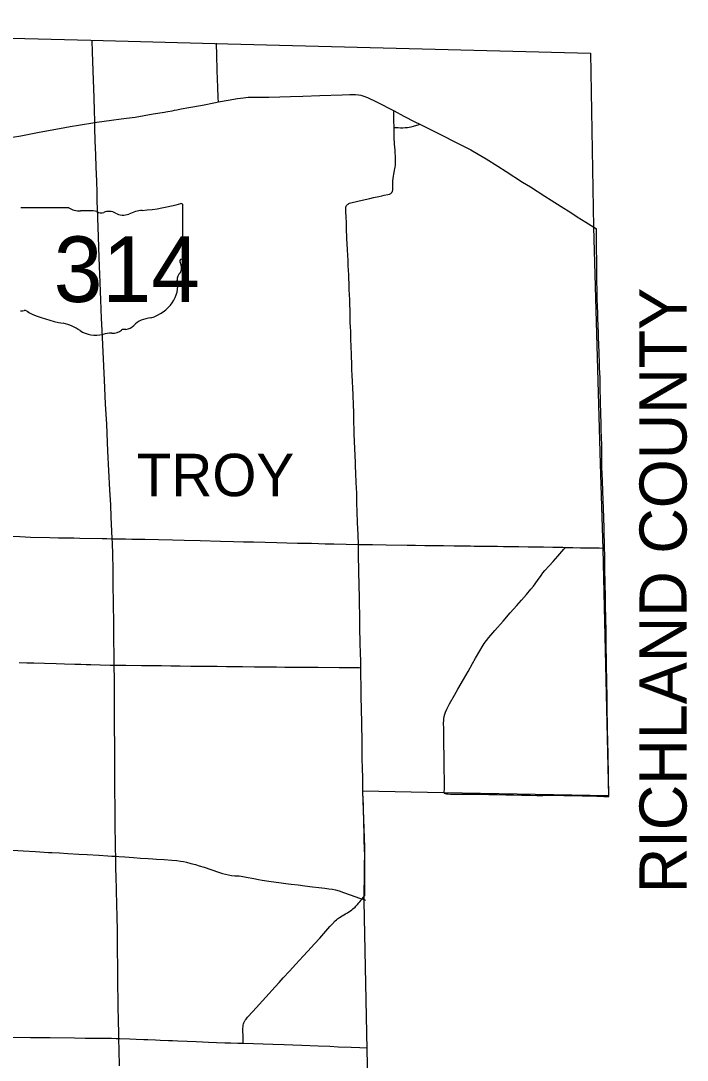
# Model space of a CAD drawing. Extents: x 1815539 to 1947826, y 273303 to 993194.
# Drawn here: x 1921002 to 1935160, y 965571 to 987636 of the extents above; entities that cross this region are included whole.
import ezdxf

# ---------------------------------------------------------------- set-up
doc = ezdxf.new("R2010")
doc.units = 0
for name, color, linetype in [('GM_X_Adjacent_County_Text', 7, 'Continuous'), ('GM_X_County', 7, 'Continuous'), ('GM_X_County_Road', 7, 'Continuous'), ('GM_X_State_Route', 7, 'Continuous'), ('GM_X_Township_Road', 7, 'Continuous'), ('GM_X_Township_Text', 7, 'Continuous'), ('SC_Shading3', 7, 'Continuous')]:
    doc.layers.add(name, color=color, linetype=linetype)

msp = doc.modelspace()

# ---------------------------------------------------------------- linework, layer by layer
at = {"layer": 'GM_X_County'}
msp.add_lwpolyline([(1905517, 987636), (1906801, 987606), (1908915, 987558), (1916031, 987559), (1916031, 987390), (1922491, 987223), (1925127, 987155), (1933106, 986948), (1933172, 983252), (1933307, 978234), (1933364, 976428), (1933485, 971181), (1929986, 971246), (1928265, 971283), (1928303, 970087), (1928288, 969028), (1928289, 968947), (1928357, 965797), (1928425, 962614)], dxfattribs=at)
at = {"layer": 'GM_X_County_Road'}
for points in [[(1919598, 976728), (1919624, 976728), (1919785, 976722), (1919899, 976717), (1920096, 976710), (1920424, 976701), (1920686, 976694), (1920981, 976685), (1921211, 976677), (1921621, 976666), (1921801, 976663), (1922129, 976658), (1922259, 976656), (1922734, 976645), (1922831, 976643), (1922947, 976639)], [(1922947, 976639), (1923098, 976636), (1923226, 976635), (1923364, 976634), (1923635, 976629), (1923930, 976624), (1924228, 976619), (1924471, 976611), (1924816, 976602), (1925242, 976589), (1925521, 976583), (1925734, 976577), (1925865, 976575), (1925947, 976573), (1926193, 976566), (1926439, 976561), (1926652, 976554), (1926881, 976549), (1927029, 976546), (1927176, 976543), (1927324, 976540), (1927471, 976535), (1927652, 976531), (1927914, 976526), (1928160, 976521), (1928175, 976521)], [(1928175, 976521), (1928291, 976518), (1928471, 976515), (1928766, 976511), (1929209, 976506), (1929390, 976503), (1929586, 976500), (1929734, 976498), (1929979, 976494), (1930209, 976490), (1930356, 976489), (1930553, 976487), (1930635, 976486), (1930717, 976486), (1930880, 976484), (1930995, 976482), (1931126, 976481), (1931257, 976479), (1931388, 976477), (1931585, 976474), (1931781, 976470), (1931896, 976468), (1932109, 976467), (1932306, 976465), (1932519, 976459), (1932572, 976457)], [(1932572, 976457), (1932733, 976453), (1932896, 976449), (1933044, 976447), (1933175, 976446), (1933290, 976445), (1933388, 976443), (1933406, 976443)], [(1920968, 974014), (1921132, 974008), (1921213, 974006), (1921279, 974005), (1921508, 973997), (1921753, 973990), (1921934, 973985), (1922147, 973979), (1922278, 973976), (1922392, 973974), (1922491, 973970), (1922687, 973964), (1922899, 973959), (1922987, 973958)], [(1920708, 966058), (1921206, 966052), (1921628, 966050), (1922140, 966044), (1922370, 966041), (1922567, 966039), (1922731, 966037), (1922928, 966037), (1923026, 966034), (1923085, 966030)], [(1923085, 966030), (1923108, 966029), (1923321, 966023), (1923452, 966017), (1923616, 966011), (1923698, 966009), (1923862, 966002), (1923960, 965996), (1924140, 965990), (1924222, 965987), (1924337, 965982), (1924534, 965974), (1924730, 965966), (1924862, 965961), (1924993, 965956), (1925157, 965950), (1925337, 965942), (1925468, 965938), (1925616, 965933), (1925725, 965931)], [(1925725, 965931), (1925730, 965931), (1925944, 965924), (1926354, 965912), (1926599, 965902), (1926779, 965895), (1926975, 965887), (1927320, 965876), (1927567, 965866), (1927745, 965858), (1928024, 965846), (1928202, 965838), (1928360, 965834)]]:
    msp.add_lwpolyline(points, dxfattribs=at)
at = {"layer": 'GM_X_State_Route'}
for points in [[(1923098, 965449), (1923091, 965777), (1923085, 966030), (1923083, 966089), (1923075, 966466), (1923071, 966663), (1923063, 967352), (1923063, 967549), (1923063, 967630), (1923062, 967663), (1923060, 967795), (1923058, 967926), (1923057, 968090), (1923055, 968320), (1923054, 968402), (1923051, 968533), (1923050, 968648), (1923045, 968845), (1923043, 968927), (1923037, 969123), (1923034, 969238), (1923029, 969418), (1923024, 969681), (1923021, 969829), (1923019, 969899), (1923015, 970042), (1923011, 970239), (1923009, 970468), (1923008, 970583), (1923008, 970714), (1923006, 970829), (1923005, 971059), (1923003, 971174), (1923002, 971239), (1923002, 971305), (1923002, 971452), (1923002, 971534), (1923000, 971649), (1922998, 971780), (1922997, 971928), (1922997, 972026), (1922999, 972223), (1922995, 972666), (1922994, 972814), (1922994, 972978), (1922994, 973125), (1922993, 973257), (1922992, 973388), (1922991, 973519), (1922991, 973634), (1922991, 973732), (1922989, 973864), (1922988, 973946), (1922987, 973958), (1922985, 974110), (1922984, 974274), (1922982, 974389), (1922979, 974651), (1922976, 974881), (1922973, 975226), (1922970, 975373), (1922966, 975570), (1922964, 975734), (1922965, 975882), (1922963, 975997), (1922958, 976309), (1922951, 976555), (1922947, 976639), (1922940, 976801), (1922925, 977096), (1922912, 977357), (1922895, 977677), (1922876, 978087), (1922855, 978496), (1922827, 979070), (1922804, 979496), (1922794, 979677), (1922782, 980004), (1922753, 980611), (1922730, 981070), (1922718, 981316), (1922702, 981709), (1922695, 981889), (1922679, 982266), (1922674, 982414), (1922661, 982824), (1922654, 983053), (1922641, 983447), (1922633, 983658), (1922628, 983793), (1922623, 983988), (1922617, 984231), (1922604, 984530), (1922596, 984790), (1922584, 985086), (1922577, 985361), (1922573, 985475), (1922572, 985511), (1922567, 985725), (1922559, 986003), (1922549, 986381), (1922527, 986971), (1922516, 987224)], [(1920826, 985162), (1921004, 985192), (1921148, 985221), (1921358, 985261), (1921551, 985296), (1921825, 985349), (1922050, 985391), (1922228, 985421), (1922573, 985475), (1922617, 985481), (1922926, 985526), (1923137, 985556), (1923251, 985569), (1923429, 985593), (1923623, 985624), (1923817, 985659), (1924054, 985697), (1924082, 985703), (1924125, 985709), (1924219, 985726), (1924267, 985735), (1924315, 985745), (1924411, 985763), (1924571, 985794), (1924862, 985847), (1925136, 985899), (1925204, 985912), (1925410, 985950), (1925604, 985984), (1925734, 986002), (1925832, 986011), (1925931, 986014), (1926275, 986012), (1926505, 986018), (1926734, 986026), (1926996, 986035), (1927357, 986048), (1927832, 986067), (1927996, 986073), (1928111, 986072), (1928177, 986066), (1928226, 986057), (1928289, 986038), (1928365, 986006), (1928557, 985912), (1928931, 985721), (1929141, 985613), (1929375, 985494), (1929480, 985441), (1929580, 985391), (1929917, 985221), (1930268, 985044), (1930560, 984894), (1930718, 984806), (1930887, 984705), (1931137, 984548), (1931317, 984434), (1931663, 984213), (1931829, 984108), (1932133, 983915), (1932272, 983828), (1932480, 983696), (1932687, 983563), (1932825, 983475), (1933005, 983361), (1933231, 983217)]]:
    msp.add_lwpolyline(points, dxfattribs=at)
at = {"layer": 'GM_X_Township_Road'}
for points in [[(1925204, 985912), (1925197, 985999), (1925185, 986237), (1925182, 986386), (1925176, 986584), (1925167, 986896), (1925160, 987157)], [(1928931, 985368), (1928929, 985524), (1928930, 985702), (1928931, 985721)], [(1928931, 985368), (1929018, 985367), (1929072, 985366), (1929119, 985366), (1929169, 985368), (1929218, 985370), (1929254, 985374), (1929297, 985384), (1929345, 985397), (1929462, 985435), (1929480, 985441)], [(1927924, 983187), (1927923, 983238), (1927922, 983306), (1927919, 983384), (1927916, 983436), (1927913, 983500), (1927909, 983550), (1927907, 983599), (1927908, 983630), (1927908, 983647), (1927909, 983664), (1927911, 983679), (1927915, 983697), (1927923, 983711), (1927932, 983724), (1927944, 983736), (1927957, 983746), (1927971, 983754), (1927986, 983761), (1928017, 983770), (1928161, 983805), (1928257, 983828), (1928417, 983865), (1928497, 983883), (1928609, 983909), (1928673, 983922), (1928721, 983933), (1928801, 983950), (1928833, 983958), (1928848, 983964), (1928863, 983972), (1928876, 983982), (1928887, 983994), (1928896, 984008), (1928902, 984023), (1928905, 984039), (1928907, 984055), (1928907, 984104), (1928906, 984187), (1928907, 984236), (1928911, 984285), (1928917, 984334), (1928925, 984382), (1928932, 984414), (1928944, 984462), (1928952, 984493), (1928958, 984525), (1928963, 984574), (1928964, 984640), (1928963, 984706), (1928953, 984886), (1928944, 985017), (1928936, 985164), (1928935, 985214), (1928931, 985368)], [(1928085, 978965), (1928080, 979106), (1928078, 979196), (1928074, 979344), (1928071, 979459), (1928061, 979704), (1928043, 980114), (1928038, 980229), (1928033, 980409), (1928031, 980457), (1928030, 980505), (1928028, 980538), (1928022, 980735), (1928016, 980866), (1928014, 980932), (1928011, 981030), (1928006, 981145), (1928003, 981227), (1927997, 981424), (1927990, 981686), (1927984, 981850), (1927981, 981899), (1927978, 981981), (1927968, 982243), (1927959, 982439), (1927954, 982538), (1927949, 982668), (1927944, 982766), (1927935, 982912), (1927931, 982994), (1927927, 983074), (1927925, 983174), (1927924, 983187)], [(1933347, 978263), (1933347, 978285), (1933346, 978384), (1933343, 978597), (1933337, 978827), (1933334, 978925), (1933331, 979105), (1933327, 979269), (1933323, 979367), (1933319, 979465), (1933317, 979562), (1933315, 979644), (1933314, 979759), (1933312, 979874), (1933310, 979989), (1933309, 980038), (1933303, 980185), (1933299, 980250), (1933297, 980300), (1933295, 980365), (1933288, 980578), (1933282, 980774), (1933278, 980905), (1933274, 981020), (1933269, 981151), (1933262, 981332), (1933259, 981446), (1933255, 981561), (1933250, 981743), (1933247, 981857), (1933244, 981953), (1933243, 982068), (1933241, 982215), (1933240, 982476), (1933238, 982590), (1933236, 982745), (1933234, 982894), (1933231, 983217)], [(1928175, 976521), (1928167, 976721), (1928157, 976984), (1928149, 977213), (1928144, 977393), (1928138, 977607), (1928130, 977836), (1928123, 978033), (1928116, 978180), (1928113, 978262), (1928107, 978409), (1928095, 978704), (1928088, 978868), (1928085, 978965)], [(1933406, 976443), (1933406, 976483), (1933401, 976614), (1933399, 976680), (1933398, 976745), (1933395, 976860), (1933388, 977089), (1933380, 977285), (1933373, 977465), (1933366, 977646), (1933359, 977875), (1933349, 978154), (1933347, 978263)], [(1928226, 973903), (1928223, 974049), (1928221, 974213), (1928214, 974426), (1928210, 974524), (1928207, 974655), (1928204, 974901), (1928196, 975377), (1928190, 975672), (1928185, 975934), (1928182, 976049), (1928180, 976197), (1928178, 976312), (1928176, 976492), (1928175, 976521)], [(1929994, 971238), (1929996, 971266), (1930001, 971325), (1930003, 971407), (1930002, 971538), (1929998, 971735), (1929996, 971882), (1929993, 972079), (1929992, 972227), (1929989, 972407), (1929988, 972604), (1929985, 972735), (1929986, 972784), (1929989, 972816), (1929998, 972865), (1930010, 972913), (1930025, 972959), (1930050, 973020), (1930072, 973064), (1930109, 973135), (1930215, 973322), (1930289, 973450), (1930404, 973649), (1930503, 973819), (1930599, 973990), (1930663, 974105), (1930753, 974261), (1930804, 974345), (1930849, 974414), (1930897, 974481), (1930948, 974545), (1931074, 974696), (1931247, 974893), (1931400, 975064), (1931541, 975224), (1931639, 975334), (1931747, 975458), (1931840, 975572), (1931891, 975637), (1931979, 975755), (1932056, 975861), (1932095, 975914), (1932137, 975964), (1932224, 976063), (1932311, 976159), (1932411, 976268), (1932497, 976367), (1932539, 976417), (1932572, 976457)], [(1933493, 971169), (1933492, 971204), (1933485, 971576), (1933477, 972069), (1933468, 972594), (1933465, 972758), (1933462, 972939), (1933458, 973217), (1933456, 973349), (1933455, 973529), (1933451, 973726), (1933448, 973841), (1933445, 974087), (1933440, 974317), (1933436, 974662), (1933431, 974973), (1933426, 975203), (1933423, 975334), (1933422, 975482), (1933419, 975613), (1933411, 976073), (1933409, 976303), (1933406, 976434), (1933406, 976443)], [(1922987, 973958), (1923237, 973956), (1923568, 973953), (1923752, 973952), (1923994, 973947), (1924187, 973942), (1924387, 973939), (1924616, 973935), (1924895, 973933), (1925092, 973933), (1925174, 973933), (1925372, 973930), (1925714, 973927), (1925967, 973924), (1926075, 973922), (1926223, 973920), (1926436, 973918), (1926615, 973916), (1926830, 973914), (1927126, 973913), (1927323, 973911), (1927765, 973909), (1928062, 973905), (1928189, 973904), (1928226, 973903)], [(1928272, 971231), (1928267, 971504), (1928267, 971592), (1928263, 971739), (1928261, 971820), (1928258, 971918), (1928256, 972131), (1928254, 972246), (1928251, 972393), (1928247, 972656), (1928244, 972787), (1928240, 972967), (1928239, 973082), (1928236, 973229), (1928232, 973475), (1928228, 973787), (1928226, 973903)], [(1928282, 970925), (1928280, 970985), (1928272, 971231)], [(1929994, 971238), (1930021, 971231), (1930047, 971227), (1930080, 971224), (1930129, 971221), (1930243, 971219), (1930358, 971218), (1930516, 971217), (1930751, 971215), (1930946, 971212), (1931129, 971210), (1931308, 971206), (1931472, 971201), (1931636, 971197), (1931833, 971194), (1931964, 971192), (1932095, 971193), (1932259, 971195), (1932407, 971194), (1932538, 971192), (1932636, 971190), (1932751, 971187), (1932930, 971181), (1932996, 971180), (1933242, 971174), (1933389, 971170), (1933452, 971169), (1933493, 971169)], [(1928295, 970413), (1928292, 970574), (1928289, 970688), (1928284, 970852), (1928282, 970925)], [(1928304, 970054), (1928302, 970100), (1928299, 970198), (1928296, 970312), (1928295, 970413)], [(1920824, 970032), (1921053, 970018), (1921315, 970002), (1921593, 969983), (1921659, 969980), (1921823, 969970), (1922003, 969960), (1922232, 969946), (1922412, 969935), (1922658, 969920), (1922854, 969910), (1922936, 969905), (1923019, 969899)], [(1928312, 969067), (1928311, 969249), (1928310, 969430), (1928311, 969528), (1928312, 969659), (1928311, 969708), (1928311, 969790), (1928309, 969920), (1928304, 970054)], [(1923019, 969899), (1923083, 969894), (1923214, 969886), (1923394, 969873), (1923542, 969862), (1923705, 969851), (1923804, 969844), (1923885, 969839), (1924049, 969829), (1924213, 969817), (1924314, 969809), (1924395, 969799), (1924458, 969788), (1924520, 969774), (1924615, 969749), (1924711, 969723), (1924790, 969700), (1924900, 969666), (1925040, 969619), (1925226, 969555), (1925289, 969536), (1925352, 969519), (1925416, 969505), (1925481, 969494), (1925547, 969488), (1925643, 969482), (1925684, 969480), (1925720, 969473), (1925791, 969458), (1925953, 969426), (1926049, 969408), (1926128, 969394), (1926274, 969371), (1926533, 969334), (1926631, 969321), (1926745, 969306), (1926892, 969290), (1927038, 969273), (1927201, 969254), (1927332, 969239), (1927462, 969223), (1927543, 969212), (1927624, 969198), (1927688, 969184), (1927767, 969164), (1927860, 969133), (1927999, 969083), (1928199, 969011), (1928253, 968993)], [(1925725, 965931), (1925725, 965969), (1925723, 966084), (1925720, 966199), (1925721, 966248), (1925723, 966281), (1925727, 966313), (1925735, 966345), (1925740, 966361), (1925745, 966376), (1925752, 966391), (1925769, 966419), (1925788, 966445), (1925820, 966483), (1925930, 966604), (1926206, 966907), (1926403, 967125), (1926491, 967223), (1926579, 967320), (1926712, 967464), (1926845, 967609), (1927000, 967777), (1927100, 967885), (1927245, 968040), (1927354, 968163), (1927484, 968310), (1927569, 968409), (1927624, 968469), (1927682, 968527), (1927706, 968549), (1927732, 968569), (1927775, 968599), (1927832, 968635), (1927897, 968676), (1927941, 968702), (1928032, 968764), (1928057, 968784), (1928103, 968821), (1928123, 968839), (1928155, 968874), (1928186, 968910), (1928207, 968936), (1928248, 968986), (1928253, 968993)], [(1928253, 968993), (1928285, 969031), (1928312, 969067)], [(1928253, 968993), (1928285, 968984), (1928323, 968969)]]:
    msp.add_lwpolyline(points, dxfattribs=at)
at = {"layer": 'SC_Shading3'}
for p, q in [((1922021, 983667), (1921002, 983667)), ((1924448, 982614), (1924448, 983719)), ((1924448, 982614), (1924448, 982614))]:
    msp.add_line(p, q, dxfattribs=at)
for centre, major_axis, start_param, end_param in [((1922264, 983912), (391, 0), 4.042523, 4.731795), ((1923208, 986548), (3691, 0), 4.814394, 5.042369), ((1924410, 983724), (38.7, 0), 6.141152, 7.989035), ((1922394, 982481), (1404, 0), 1.404758, 1.657858), ((1922713, 983646), (113, 0), 3.836095, 5.185415), ((1922878, 983402), (235, 0), 0.950623, 2.079405), ((1923181, 983737), (282, 0), 4.081561, 5.145723), ((1923679, 983022), (743, 0), 1.699011, 2.107814), ((1924439, 982533), (60, 0), 1.883978, 3.671073), ((1924407, 982610), (41.5, 0), 5.05454, 6.418171), ((1924058, 982393), (360, 0), 5.934695, 6.695948), ((1923415, 982011), (923, 0), 5.101752, 6.440018), ((1924587, 982151), (262, 0), 2.387724, 3.262537), ((1921014, 981729), (310, 0), 4.665946, 4.897461), ((1921078, 981395), (112, 0), 0.519207, 1.627899), ((1922491, 983294), (2665, 0), 4.195997, 4.488961), ((1923804, 980924), (506, 0), 1.647645, 2.488434), ((1921696, 980568), (834, 0), 0.823519, 1.323587), ((1922598, 981385), (529, 0), 4.026481, 4.996735), ((1922943, 981227), (282, 0), 4.691044, 5.507374), ((1923198, 981022), (79.4, 0), 1.147584, 2.315152), ((1923164, 981313), (298, 0), 4.937069, 5.64225), ((1922904, 980654), (435, 0), 1.495662, 1.94098)]:
    msp.add_ellipse(centre, major_axis=major_axis, ratio=0.8, start_param=start_param, end_param=end_param, dxfattribs=at)

# ---------------------------------------------------------------- texts
at = {"layer": 'GM_X_Adjacent_County_Text'}
msp.add_text('RICHLAND COUNTY', height=1000, rotation=90, dxfattribs=at).set_placement((1935146, 969115))
at = {"layer": 'GM_X_Township_Text'}
msp.add_text('TROY', height=900, rotation=0, dxfattribs=at).set_placement((1923467, 977544))
at = {"layer": 'SC_Shading3'}
msp.add_text('314', height=1392.2, dxfattribs=at).set_placement((1921702, 981666))

doc.saveas('drawing.dxf')
